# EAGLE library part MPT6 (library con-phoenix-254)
PHOENIX CONNECTOR
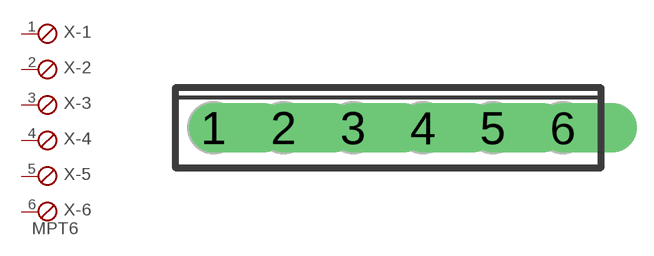
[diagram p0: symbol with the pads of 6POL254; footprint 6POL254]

Designator prefix X; gates -1=SKB -2=SKB -3=SKB -4=SKB -5=SKB -6=SKBV

## MPT6  [6POL254]
1  -1:1  pas
2  -2:1  pas
3  -3:1  pas
4  -4:1  pas
5  -5:1  pas
6  -6:1  pas

## Footprint 6POL254 (pad centres in mm)
PHOENIX CONNECTOR
drill 1.2 pad 1.778 offset: 1 -6.35,0; 2 -3.81,0; 3 -1.27,0; 4 1.27,0; 5 3.81,0; 6 6.35,0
